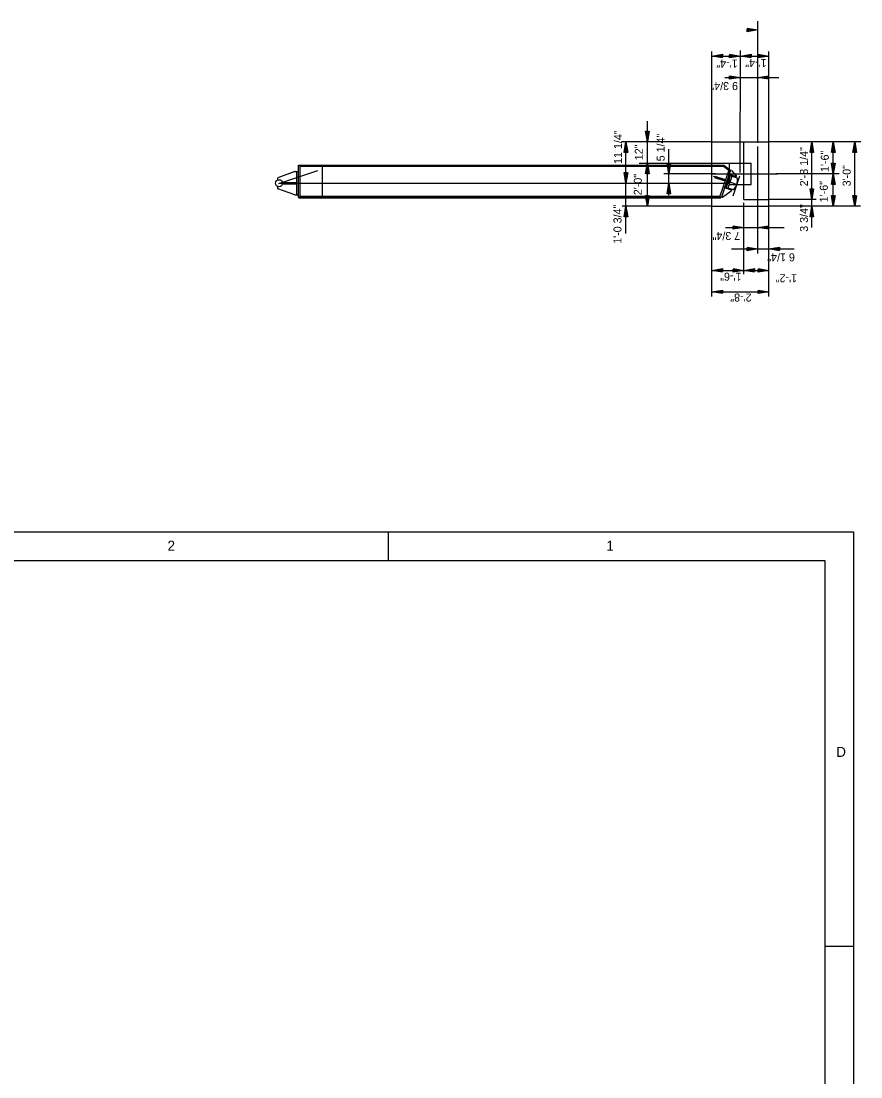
# Model space of a CAD drawing. Extents: x -48 to 108, y -5 to 100.
# Drawn here: x 69.16 to 108.31, y 50.53 to 99.78 of the extents above; entities that cross this region are included whole.
import ezdxf

# ---------------------------------------------------------------- set-up
doc = ezdxf.new("R2010")
doc.units = 0
for name, color, linetype in [('Level 1', 7, 'Continuous'), ('Level 25', 7, 'Continuous'), ('Level 50', 7, 'Continuous')]:
    doc.layers.add(name, color=color, linetype=linetype)

msp = doc.modelspace()

# ---------------------------------------------------------------- linework, layer by layer
at = {"layer": 'Level 1'}
for p, q in [((86.292, 74.625), (86.292, 75.958)), ((106.625, 56.625), (107.958, 56.625))]:
    msp.add_line(p, q, dxfattribs=at)
for points in [[(1.292, 75.958), (107.958, 75.958), (107.958, 1.292), (1.292, 1.292)], [(5.292, 74.625), (106.625, 74.625), (106.625, 2.625), (5.292, 2.625)]]:
    msp.add_lwpolyline(points, close=True, dxfattribs=at)
at = {"layer": 'Level 25'}
for p, q in [((103.502, 97.374), (103.502, 99.778)), ((101.356, 94.15), (101.356, 98.364)), ((101.356, 98.15), (102.69, 98.15)), ((102.689, 92.71), (102.69, 98.409)), ((102.69, 98.15), (104.023, 98.15)), ((104.023, 94.15), (104.023, 98.364)), ((101.966, 97.15), (102.69, 97.15)), ((102.69, 97.15), (103.502, 97.15)), ((103.502, 94.106), (103.502, 97.374)), ((103.502, 97.15), (104.477, 97.15)), ((98.356, 94.15), (98.356, 95.115)), ((101.356, 94.15), (97.152, 94.15)), ((97.356, 92.213), (97.356, 94.15)), ((98.356, 93.151), (98.356, 94.15)), ((101.356, 94.15), (104.023, 94.15)), ((101.356, 91.15), (101.356, 94.15)), ((102.856, 92.193), (102.856, 94.106)), ((104.022, 91.15), (104.023, 94.15)), ((108.308, 94.15), (104.023, 94.15)), ((106.022, 91.463), (106.023, 94.15)), ((107.023, 92.65), (107.023, 94.15)), ((108.022, 91.15), (108.023, 94.15)), ((99.356, 92.651), (99.356, 93.8)), ((103.502, 91.261), (103.502, 93.928)), ((97.981, 93.151), (101.356, 93.15)), ((98.356, 91.15), (98.356, 93.151)), ((101.356, 93.15), (102.856, 93.15)), ((102.189, 92.15), (102.189, 93.15)), ((102.189, 93.15), (103.189, 93.15)), ((102.856, 91.463), (102.856, 93.15)), ((103.189, 92.15), (103.189, 93.15)), ((81.925, 92.757), (81.134, 92.476)), ((81.171, 92.209), (82.987, 92.814)), ((81.925, 92.757), (82.092, 92.757)), ((82.009, 91.673), (82.009, 92.757)), ((82.092, 93.064), (101.922, 93.062)), ((82.092, 91.564), (82.092, 93.064)), ((82.175, 91.564), (82.175, 93.064)), ((82.175, 93.017), (101.905, 93.015)), ((83.207, 91.544), (83.207, 93.044)), ((101.534, 92.651), (99.118, 92.651)), ((99.356, 92.213), (99.356, 92.651)), ((101.368, 92.65), (104.424, 92.65)), ((102.165, 92.879), (101.726, 91.562)), ((102.236, 92.827), (101.814, 91.562)), ((101.922, 93.061), (101.906, 93.014)), ((101.906, 93.014), (102.149, 92.832)), ((101.922, 93.061), (102.236, 92.827)), ((102.157, 92.59), (102.078, 92.616)), ((102.552, 92.458), (102.157, 92.589)), ((102.486, 92.524), (102.17, 92.63)), ((102.486, 92.524), (102.17, 92.629)), ((102.552, 92.458), (102.193, 92.578)), ((102.275, 92.813), (102.236, 92.827)), ((102.275, 92.813), (102.499, 92.564)), ((107.302, 92.65), (104.341, 92.65)), ((107.022, 91.15), (107.023, 92.65)), ((81.134, 92.374), (81.134, 92.476)), ((81.191, 92.215), (102.147, 92.213)), ((81.348, 92.246), (82.009, 92.246)), ((81.348, 92.184), (82.009, 92.184)), ((97.356, 91.15), (97.356, 92.213)), ((99.356, 91.657), (99.356, 92.213)), ((102.611, 92.131), (101.434, 92.524)), ((102.611, 92.131), (101.434, 92.524)), ((101.521, 92.527), (101.501, 92.468)), ((101.976, 92.31), (101.501, 92.468)), ((101.995, 92.369), (101.521, 92.527)), ((102.216, 92.57), (102.031, 92.017)), ((102.295, 92.544), (102.111, 91.99)), ((102.189, 92.15), (103.189, 92.15)), ((102.647, 92.546), (102.335, 91.61)), ((102.499, 92.564), (102.473, 92.485)), ((102.499, 92.564), (102.473, 92.484)), ((81.134, 91.955), (81.134, 92.056)), ((81.925, 91.673), (81.134, 91.955)), ((81.925, 91.673), (82.092, 91.673)), ((82.175, 91.611), (101.742, 91.609)), ((101.492, 91.562), (101.492, 91.609)), ((102.262, 91.852), (101.854, 91.549)), ((101.972, 92.037), (101.893, 92.063)), ((102.275, 91.892), (101.959, 91.997)), ((102.367, 91.905), (101.972, 92.037)), ((102.288, 91.931), (102.262, 91.852)), ((82.092, 91.564), (101.814, 91.562)), ((82.113, 91.538), (82.113, 91.564)), ((82.113, 91.538), (101.783, 91.536)), ((101.356, 91.15), (97.175, 91.15)), ((97.356, 89.879), (97.356, 91.15)), ((101.356, 91.15), (104.022, 91.15)), ((101.356, 86.937), (101.356, 91.15)), ((101.792, 91.562), (101.783, 91.536)), ((101.854, 91.549), (101.814, 91.562)), ((102.856, 91.463), (104.022, 91.463)), ((102.856, 87.979), (102.856, 91.31)), ((103.501, 88.935), (103.502, 91.261)), ((105.727, 91.463), (104.022, 91.463)), ((104.022, 86.937), (104.022, 91.15)), ((108.285, 91.15), (104.022, 91.15)), ((106.231, 91.463), (105.331, 91.463)), ((106.022, 91.15), (106.022, 91.463)), ((106.022, 90.147), (106.022, 91.15)), ((106.022, 90.147), (106.022, 91.15)), ((102.002, 90.15), (102.856, 90.15)), ((102.856, 90.15), (103.501, 90.15)), ((103.501, 90.15), (104.726, 90.15)), ((102.274, 89.15), (103.501, 89.15)), ((103.501, 89.15), (104.022, 89.15)), ((104.022, 89.15), (105.2, 89.15)), ((101.356, 88.15), (102.856, 88.15)), ((102.856, 88.15), (104.022, 88.15)), ((101.356, 87.15), (104.022, 87.15))]:
    msp.add_line(p, q, dxfattribs=at)
msp.add_circle((81.184, 92.215), 0.167, dxfattribs=at)
msp.add_arc((101.844, 92.387), 0.712, 317.3695, 5.7486, dxfattribs=at)
at = {"layer": 'Level 50'}
for p, q in [((103.363, 99.366), (103.363, 99.366)), ((103.502, 99.366), (103.502, 99.366)), ((101.356, 98.15), (101.356, 98.15)), ((101.495, 98.15), (101.495, 98.15)), ((102.551, 98.15), (102.551, 98.15)), ((102.69, 98.15), (102.69, 98.15)), ((102.69, 98.15), (102.69, 98.15)), ((102.828, 98.15), (102.828, 98.15)), ((103.884, 98.15), (103.884, 98.15)), ((104.023, 98.15), (104.023, 98.15)), ((102.551, 97.15), (102.551, 97.15)), ((102.69, 97.15), (102.69, 97.15)), ((103.502, 97.15), (103.502, 97.15)), ((103.641, 97.15), (103.641, 97.15)), ((97.356, 94.15), (97.356, 94.15)), ((98.356, 94.289), (98.356, 94.289)), ((98.356, 94.15), (98.356, 94.15)), ((106.023, 94.15), (106.023, 94.15)), ((107.023, 94.15), (107.023, 94.15)), ((108.023, 94.15), (108.023, 94.15)), ((97.356, 94.012), (97.356, 94.012)), ((106.023, 94.011), (106.023, 94.011)), ((107.023, 94.012), (107.023, 94.012)), ((108.023, 94.012), (108.023, 94.012)), ((98.356, 93.151), (98.356, 93.151)), ((98.356, 93.012), (98.356, 93.012)), ((99.356, 92.789), (99.356, 92.789)), ((99.356, 92.651), (99.356, 92.651)), ((107.023, 92.789), (107.023, 92.789)), ((107.023, 92.65), (107.023, 92.65)), ((107.023, 92.65), (107.023, 92.65)), ((97.356, 92.352), (97.356, 92.352)), ((97.356, 92.213), (97.356, 92.213)), ((99.356, 92.213), (99.356, 92.213)), ((107.023, 92.511), (107.023, 92.511)), ((99.356, 92.075), (99.356, 92.075)), ((106.022, 91.601), (106.022, 91.601)), ((97.356, 91.15), (97.356, 91.15)), ((98.356, 91.289), (98.356, 91.289)), ((98.356, 91.15), (98.356, 91.15)), ((106.022, 91.463), (106.022, 91.463)), ((106.022, 91.15), (106.022, 91.15)), ((107.022, 91.289), (107.022, 91.289)), ((107.022, 91.15), (107.022, 91.15)), ((108.022, 91.289), (108.022, 91.289)), ((108.022, 91.15), (108.022, 91.15)), ((97.356, 91.012), (97.356, 91.012)), ((106.022, 91.012), (106.022, 91.012)), ((102.717, 90.15), (102.717, 90.15)), ((102.856, 90.15), (102.856, 90.15)), ((103.501, 90.15), (103.501, 90.15)), ((103.64, 90.15), (103.64, 90.15)), ((103.363, 89.15), (103.363, 89.15)), ((103.501, 89.15), (103.501, 89.15)), ((104.022, 89.15), (104.022, 89.15)), ((104.161, 89.15), (104.161, 89.15)), ((101.356, 88.15), (101.356, 88.15)), ((101.494, 88.15), (101.494, 88.15)), ((102.717, 88.15), (102.717, 88.15)), ((102.856, 88.15), (102.856, 88.15)), ((102.856, 88.15), (102.856, 88.15)), ((102.995, 88.15), (102.995, 88.15)), ((103.884, 88.15), (103.884, 88.15)), ((104.022, 88.15), (104.022, 88.15)), ((101.356, 87.15), (101.356, 87.15)), ((101.494, 87.15), (101.494, 87.15)), ((103.884, 87.15), (103.884, 87.15)), ((104.022, 87.15), (104.022, 87.15))]:
    msp.add_line(p, q, dxfattribs=at)
for points in [[(103.003, 99.448), (103.502, 99.366), (103.003, 99.283), (103.003, 99.424), (103.363, 99.366), (103.025, 99.31), (103.025, 99.4), (103.23, 99.366), (103.046, 99.336), (103.046, 99.374), (103.091, 99.366)], [(101.855, 98.068), (101.356, 98.15), (101.855, 98.233), (101.855, 98.092), (101.495, 98.15), (101.833, 98.206), (101.833, 98.116), (101.628, 98.15), (101.812, 98.18), (101.812, 98.142), (101.767, 98.15)], [(102.191, 98.233), (102.69, 98.15), (102.191, 98.068), (102.191, 98.209), (102.551, 98.15), (102.212, 98.094), (102.212, 98.185), (102.418, 98.15), (102.234, 98.121), (102.234, 98.158), (102.279, 98.15)], [(103.188, 98.068), (102.69, 98.15), (103.188, 98.233), (103.188, 98.092), (102.828, 98.15), (103.167, 98.206), (103.167, 98.116), (102.962, 98.15), (103.146, 98.18), (103.146, 98.142), (103.1, 98.15)], [(103.524, 98.233), (104.023, 98.15), (103.524, 98.068), (103.524, 98.209), (103.884, 98.15), (103.546, 98.094), (103.546, 98.185), (103.751, 98.15), (103.567, 98.121), (103.567, 98.158), (103.612, 98.15)], [(102.191, 97.233), (102.69, 97.15), (102.191, 97.068), (102.191, 97.209), (102.551, 97.15), (102.212, 97.094), (102.212, 97.185), (102.418, 97.15), (102.234, 97.121), (102.234, 97.158), (102.279, 97.15)], [(104.001, 97.068), (103.502, 97.15), (104.001, 97.233), (104.001, 97.092), (103.641, 97.15), (103.979, 97.206), (103.979, 97.116), (103.774, 97.15), (103.958, 97.18), (103.958, 97.142), (103.913, 97.15)], [(98.439, 94.649), (98.356, 94.15), (98.273, 94.649), (98.415, 94.649), (98.356, 94.289), (98.3, 94.628), (98.391, 94.628), (98.356, 94.422), (98.327, 94.606), (98.364, 94.606), (98.356, 94.561)], [(97.273, 93.652), (97.356, 94.15), (97.439, 93.652), (97.297, 93.652), (97.356, 94.012), (97.412, 93.673), (97.321, 93.673), (97.356, 93.878), (97.385, 93.694), (97.348, 93.694), (97.356, 93.74)], [(105.94, 93.651), (106.023, 94.15), (106.105, 93.651), (105.964, 93.651), (106.023, 94.011), (106.079, 93.673), (105.988, 93.673), (106.023, 93.878), (106.052, 93.694), (106.015, 93.694), (106.023, 93.739)], [(106.94, 93.652), (107.023, 94.15), (107.105, 93.652), (106.964, 93.652), (107.023, 94.012), (107.079, 93.673), (106.988, 93.673), (107.023, 93.878), (107.052, 93.694), (107.015, 93.694), (107.023, 93.74)], [(107.94, 93.652), (108.023, 94.15), (108.105, 93.652), (107.964, 93.652), (108.023, 94.012), (108.079, 93.673), (107.988, 93.673), (108.023, 93.878), (108.052, 93.694), (108.015, 93.694), (108.023, 93.74)], [(98.273, 92.652), (98.356, 93.151), (98.439, 92.652), (98.297, 92.652), (98.356, 93.012), (98.412, 92.673), (98.321, 92.673), (98.356, 92.879), (98.385, 92.695), (98.348, 92.695), (98.356, 92.74)], [(99.439, 93.149), (99.356, 92.651), (99.273, 93.149), (99.415, 93.149), (99.356, 92.789), (99.3, 93.128), (99.391, 93.128), (99.356, 92.923), (99.327, 93.107), (99.364, 93.107), (99.356, 93.061)], [(107.105, 93.149), (107.023, 92.65), (106.94, 93.149), (107.081, 93.149), (107.023, 92.789), (106.967, 93.127), (107.057, 93.127), (107.023, 92.922), (106.993, 93.106), (107.031, 93.106), (107.023, 93.061)], [(97.439, 92.712), (97.356, 92.213), (97.273, 92.712), (97.415, 92.712), (97.356, 92.352), (97.3, 92.691), (97.391, 92.691), (97.356, 92.485), (97.327, 92.669), (97.364, 92.669), (97.356, 92.624)], [(106.94, 92.151), (107.023, 92.65), (107.105, 92.151), (106.964, 92.151), (107.023, 92.511), (107.079, 92.173), (106.988, 92.173), (107.023, 92.378), (107.052, 92.194), (107.015, 92.194), (107.023, 92.239)], [(99.273, 91.715), (99.356, 92.213), (99.438, 91.715), (99.297, 91.715), (99.356, 92.075), (99.412, 91.736), (99.321, 91.736), (99.356, 91.941), (99.385, 91.757), (99.348, 91.757), (99.356, 91.803)], [(98.438, 91.649), (98.356, 91.15), (98.273, 91.649), (98.414, 91.649), (98.356, 91.289), (98.3, 91.628), (98.39, 91.628), (98.356, 91.422), (98.326, 91.606), (98.364, 91.606), (98.356, 91.561)], [(106.105, 91.961), (106.022, 91.463), (105.94, 91.961), (106.081, 91.961), (106.022, 91.601), (105.967, 91.94), (106.057, 91.94), (106.022, 91.735), (105.993, 91.919), (106.031, 91.919), (106.022, 91.873)], [(107.105, 91.649), (107.022, 91.15), (106.94, 91.649), (107.081, 91.649), (107.022, 91.289), (106.966, 91.628), (107.057, 91.628), (107.022, 91.422), (106.993, 91.606), (107.03, 91.606), (107.022, 91.561)], [(108.105, 91.649), (108.022, 91.15), (107.94, 91.649), (108.081, 91.649), (108.022, 91.289), (107.966, 91.628), (108.057, 91.628), (108.022, 91.422), (107.993, 91.606), (108.03, 91.606), (108.022, 91.561)], [(97.273, 90.652), (97.356, 91.15), (97.438, 90.652), (97.297, 90.652), (97.356, 91.012), (97.412, 90.673), (97.321, 90.673), (97.356, 90.878), (97.385, 90.694), (97.348, 90.694), (97.356, 90.74)], [(105.94, 90.652), (106.022, 91.15), (106.105, 90.652), (105.964, 90.652), (106.022, 91.012), (106.078, 90.673), (105.988, 90.673), (106.022, 90.878), (106.052, 90.694), (106.014, 90.694), (106.022, 90.74)], [(102.357, 90.233), (102.856, 90.15), (102.357, 90.068), (102.357, 90.209), (102.717, 90.15), (102.378, 90.094), (102.379, 90.185), (102.584, 90.15), (102.4, 90.121), (102.4, 90.158), (102.445, 90.15)], [(104, 90.068), (103.501, 90.15), (104, 90.233), (104, 90.092), (103.64, 90.15), (103.979, 90.206), (103.979, 90.116), (103.773, 90.15), (103.957, 90.18), (103.957, 90.142), (103.912, 90.15)], [(103.003, 89.233), (103.501, 89.15), (103.003, 89.068), (103.003, 89.209), (103.363, 89.15), (103.024, 89.094), (103.024, 89.185), (103.229, 89.15), (103.045, 89.121), (103.045, 89.158), (103.091, 89.15)], [(104.521, 89.067), (104.022, 89.15), (104.521, 89.233), (104.521, 89.091), (104.161, 89.15), (104.5, 89.206), (104.5, 89.115), (104.294, 89.15), (104.478, 89.179), (104.478, 89.142), (104.433, 89.15)], [(101.854, 88.068), (101.356, 88.15), (101.854, 88.233), (101.854, 88.092), (101.494, 88.15), (101.833, 88.206), (101.833, 88.116), (101.628, 88.15), (101.812, 88.18), (101.812, 88.142), (101.766, 88.15)], [(102.357, 88.233), (102.856, 88.15), (102.357, 88.068), (102.357, 88.209), (102.717, 88.15), (102.378, 88.094), (102.379, 88.185), (102.584, 88.15), (102.4, 88.121), (102.4, 88.158), (102.445, 88.15)], [(103.354, 88.068), (102.856, 88.15), (103.355, 88.233), (103.354, 88.092), (102.995, 88.15), (103.333, 88.206), (103.333, 88.116), (103.128, 88.15), (103.312, 88.18), (103.312, 88.142), (103.267, 88.15)], [(103.524, 88.233), (104.022, 88.15), (103.524, 88.068), (103.524, 88.209), (103.884, 88.15), (103.545, 88.094), (103.545, 88.185), (103.75, 88.15), (103.566, 88.121), (103.566, 88.158), (103.612, 88.15)], [(101.854, 87.068), (101.356, 87.15), (101.854, 87.233), (101.854, 87.092), (101.494, 87.15), (101.833, 87.206), (101.833, 87.116), (101.628, 87.15), (101.812, 87.18), (101.812, 87.142), (101.766, 87.15)], [(103.524, 87.233), (104.022, 87.15), (103.524, 87.068), (103.524, 87.209), (103.884, 87.15), (103.545, 87.094), (103.545, 87.185), (103.75, 87.15), (103.566, 87.121), (103.566, 87.158), (103.612, 87.15)]]:
    msp.add_lwpolyline(points, dxfattribs=at)

# ---------------------------------------------------------------- texts
at = {"layer": 'Level 1'}
for s, p in [('2', (75.99, 75.076)), ('1', (96.441, 75.075)), ('D', (107.161, 65.461))]:
    msp.add_text(s, height=0.467, dxfattribs=at).set_placement(p)
at = {"layer": 'Level 25'}
for s, rotation, p in [('1\'-4"', 180, (103.915, 98.006)), ('1\'-4"', 180, (102.565, 97.982)), ('9 3/4"', 180, (102.58, 96.935)), ('11 1/4"', 90, (97.173, 93.117)), ('5 1/4"', 90, (99.162, 93.239)), ('12"', 90, (98.144, 93.29)), ('2\'-8 1/4"', 90, (105.842, 92.072)), ('1\'-6"', 90, (106.813, 92.74)), ('2\'-0"', 90, (98.096, 91.657)), ('3\'-0"', 90, (107.832, 92.071)), ('1\'-6"', 90, (106.766, 91.327)), ('1\'-0 3/4"', 90, (97.149, 89.389)), ('3 3/4"', 90, (105.842, 89.951)), ('7 3/4"', 180, (102.684, 89.945)), ('6 1/4"', 180, (105.233, 88.946)), ('1\'-6"', 180, (102.745, 88.045)), ('1\'-2"', 180, (105.336, 87.972)), ('2\'-8"', 180, (103.216, 87.071))]:
    msp.add_text(s, height=0.3733, rotation=rotation, dxfattribs=at).set_placement(p)

doc.saveas('drawing.dxf')
